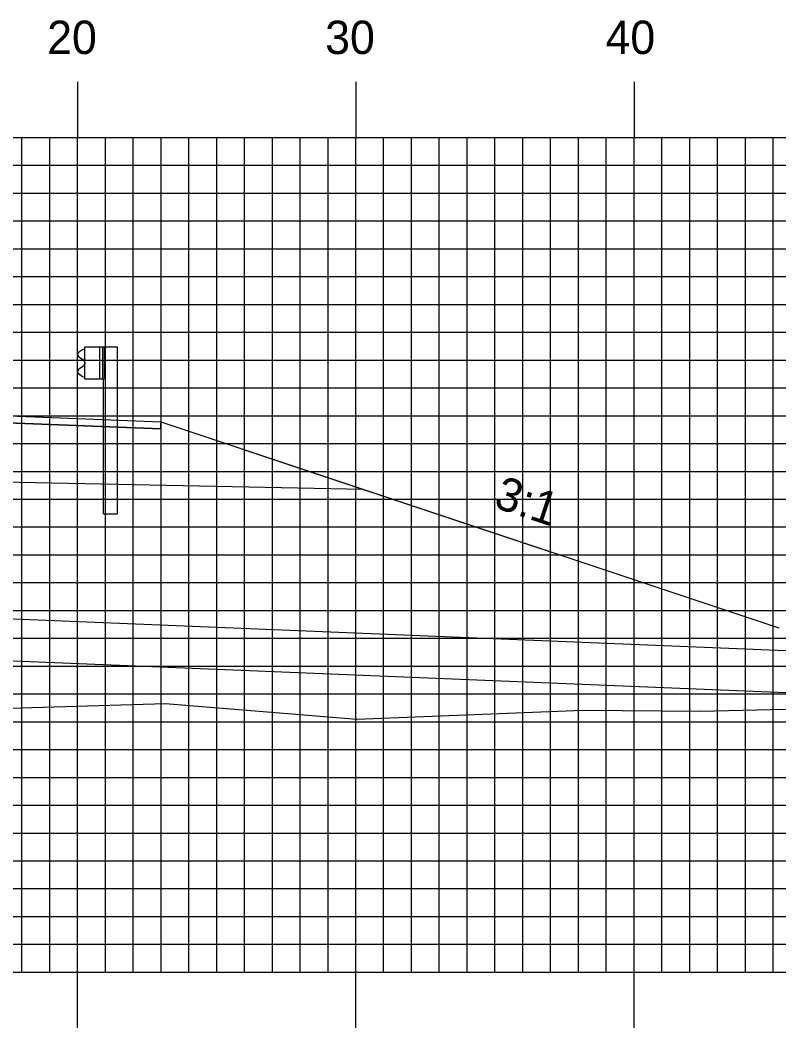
# Model space of a CAD drawing. Extents: x 1775564 to 1775907, y 442591 to 442811.
# Drawn here: x 1775747.65 to 1775774.91, y 442731.66 to 442767.88 of the extents above; entities that cross this region are included whole.
import ezdxf

# ---------------------------------------------------------------- set-up
doc = ezdxf.new("R2010")
doc.units = 0
for name, color, linetype in [('ANNOTATION', 7, 'Continuous'), ('D_Drainage_Culvert', 7, 'Continuous'), ('D_Guardrail_Beam_Rt', 7, 'Continuous'), ('D_Roadway_Centerline', 7, 'Continuous'), ('D_Roadway_Edge_Shoulder', 7, 'Continuous'), ('D_Roadway_SlopeLines', 7, 'Continuous'), ('D_Roadway_SubGrade', 7, 'Continuous'), ('H_V ANNOTATION', 7, 'Continuous'), ('MAJOR', 7, 'Continuous'), ('MINOR', 7, 'Continuous'), ('S_Roadway_Centerline', 7, 'Continuous')]:
    doc.layers.add(name, color=color, linetype=linetype)

msp = doc.modelspace()

# ---------------------------------------------------------------- linework, layer by layer
at = {"layer": 'D_Drainage_Culvert'}
for p, q in [((1775780.029, 442745.014), (1775684.11, 442748.945)), ((1775684.048, 442747.446), (1775779.968, 442743.515))]:
    msp.add_line(p, q, dxfattribs=at)
at = {"layer": 'D_Guardrail_Beam_Rt'}
for p, q in [((1775749.977, 442756.059), (1775749.903, 442756.044)), ((1775749.977, 442756.142), (1775750.665, 442756.142)), ((1775749.977, 442754.975), (1775749.977, 442756.142)), ((1775750.498, 442756.142), (1775750.498, 442754.975)), ((1775750.602, 442756.142), (1775750.602, 442754.975)), ((1775750.665, 442756.142), (1775751.136, 442756.142)), ((1775750.665, 442756.142), (1775750.665, 442754.975)), ((1775751.136, 442756.142), (1775751.136, 442750.142)), ((1775749.887, 442756.038), (1775749.744, 442755.938)), ((1775749.744, 442755.794), (1775749.939, 442755.658)), ((1775749.939, 442755.459), (1775749.744, 442755.323)), ((1775749.973, 442755.594), (1775749.973, 442755.524)), ((1775749.744, 442755.18), (1775749.887, 442755.08)), ((1775749.903, 442755.073), (1775749.977, 442755.059)), ((1775750.665, 442754.975), (1775749.977, 442754.975)), ((1775750.644, 442750.142), (1775750.644, 442754.975)), ((1775750.644, 442750.142), (1775751.136, 442750.142))]:
    msp.add_line(p, q, dxfattribs=at)
for centre, major_axis, start_param, end_param in [((1775749.911, 442756.004), (-0.0417, 0), 4.907132, 5.323254), ((1775749.794, 442755.866), (-0.0877, 0), 5.323254, 7.243116), ((1775749.794, 442755.252), (-0.0877, 0), 5.323254, 7.243116), ((1775749.894, 442755.594), (0.0789, 0), 0, 0.959931), ((1775749.894, 442755.524), (0.0789, 0), 5.323254, 6.283185), ((1775749.911, 442755.114), (-0.0417, 0), 0.959931, 1.376053)]:
    msp.add_ellipse(centre, major_axis=major_axis, ratio=0.995501, start_param=start_param, end_param=end_param, dxfattribs=at)
at = {"layer": 'D_Roadway_Centerline'}
msp.add_lwpolyline([(1775688.612, 442749.728), (1775693.913, 442750.903), (1775705.062, 442753.373), (1775705.062, 442753.373), (1775705.066, 442753.373), (1775709.262, 442753.541), (1775717.699, 442753.879), (1775717.706, 442753.879), (1775717.713, 442753.879), (1775724.629, 442754.017), (1775729.701, 442754.119), (1775729.706, 442754.119), (1775729.711, 442754.119), (1775741.706, 442753.879), (1775749.707, 442753.559), (1775752.706, 442753.439), (1775758.651, 442751.456), (1775758.652, 442751.456), (1775774.914, 442746.036)], dxfattribs=at)
at = {"layer": 'D_Roadway_Edge_Shoulder'}
msp.add_lwpolyline([(1775741.706, 442753.879), (1775749.706, 442753.559), (1775749.706, 442753.559), (1775752.706, 442753.439), (1775752.706, 442753.189), (1775741.706, 442753.629)], close=True, dxfattribs=at)
at = {"layer": 'D_Roadway_SlopeLines'}
msp.add_lwpolyline([(1775752.706, 442753.439), (1775774.912, 442746.037)], dxfattribs=at)
at = {"layer": 'D_Roadway_SubGrade'}
msp.add_lwpolyline([(1775741.706, 442753.629), (1775752.706, 442753.189), (1775752.706, 442753.439), (1775759.981, 442751.013), (1775741.706, 442751.378)], close=True, dxfattribs=at)
at = {"layer": 'MAJOR'}
for p, q in [((1775749.711, 442765.669), (1775749.711, 442763.665)), ((1775759.711, 442765.669), (1775759.711, 442763.665)), ((1775769.711, 442765.669), (1775769.711, 442763.665)), ((1775589.711, 442763.665), (1775869.711, 442763.665)), ((1775589.711, 442763.665), (1775869.711, 442763.665)), ((1775749.711, 442733.665), (1775749.711, 442763.665)), ((1775759.711, 442733.665), (1775759.711, 442763.665)), ((1775769.711, 442733.665), (1775769.711, 442763.665)), ((1775589.711, 442758.665), (1775869.711, 442758.665)), ((1775589.711, 442753.665), (1775869.711, 442753.665)), ((1775589.711, 442748.665), (1775869.711, 442748.665)), ((1775589.711, 442743.665), (1775869.711, 442743.665)), ((1775589.711, 442738.665), (1775869.711, 442738.665)), ((1775589.711, 442733.665), (1775869.711, 442733.665)), ((1775589.711, 442733.665), (1775869.711, 442733.665)), ((1775749.711, 442731.661), (1775749.711, 442733.665)), ((1775759.711, 442731.661), (1775759.711, 442733.665)), ((1775769.711, 442731.661), (1775769.711, 442733.665))]:
    msp.add_line(p, q, dxfattribs=at)
at = {"layer": 'MINOR'}
for p, q in [((1775747.711, 442733.665), (1775747.711, 442763.665)), ((1775748.711, 442733.665), (1775748.711, 442763.665)), ((1775750.711, 442733.665), (1775750.711, 442763.665)), ((1775751.711, 442733.665), (1775751.711, 442763.665)), ((1775752.711, 442733.665), (1775752.711, 442763.665)), ((1775753.711, 442733.665), (1775753.711, 442763.665)), ((1775754.711, 442733.665), (1775754.711, 442763.665)), ((1775755.711, 442733.665), (1775755.711, 442763.665)), ((1775756.711, 442733.665), (1775756.711, 442763.665)), ((1775757.711, 442733.665), (1775757.711, 442763.665)), ((1775758.711, 442733.665), (1775758.711, 442763.665)), ((1775760.711, 442733.665), (1775760.711, 442763.665)), ((1775761.711, 442733.665), (1775761.711, 442763.665)), ((1775762.711, 442733.665), (1775762.711, 442763.665)), ((1775763.711, 442733.665), (1775763.711, 442763.665)), ((1775764.711, 442733.665), (1775764.711, 442763.665)), ((1775765.711, 442733.665), (1775765.711, 442763.665)), ((1775766.711, 442733.665), (1775766.711, 442763.665)), ((1775767.711, 442733.665), (1775767.711, 442763.665)), ((1775768.711, 442733.665), (1775768.711, 442763.665)), ((1775770.711, 442733.665), (1775770.711, 442763.665)), ((1775771.711, 442733.665), (1775771.711, 442763.665)), ((1775772.711, 442733.665), (1775772.711, 442763.665)), ((1775773.711, 442733.665), (1775773.711, 442763.665)), ((1775774.711, 442733.665), (1775774.711, 442763.665)), ((1775589.711, 442762.665), (1775869.711, 442762.665)), ((1775589.711, 442761.665), (1775869.711, 442761.665)), ((1775589.711, 442760.665), (1775869.711, 442760.665)), ((1775589.711, 442759.665), (1775869.711, 442759.665)), ((1775589.711, 442757.665), (1775869.711, 442757.665)), ((1775589.711, 442756.665), (1775869.711, 442756.665)), ((1775589.711, 442755.665), (1775869.711, 442755.665)), ((1775589.711, 442754.665), (1775869.711, 442754.665)), ((1775589.711, 442752.665), (1775869.711, 442752.665)), ((1775589.711, 442751.665), (1775869.711, 442751.665)), ((1775589.711, 442750.665), (1775869.711, 442750.665)), ((1775589.711, 442749.665), (1775869.711, 442749.665)), ((1775589.711, 442747.665), (1775869.711, 442747.665)), ((1775589.711, 442746.665), (1775869.711, 442746.665)), ((1775589.711, 442745.665), (1775869.711, 442745.665)), ((1775589.711, 442744.665), (1775869.711, 442744.665)), ((1775589.711, 442742.665), (1775869.711, 442742.665)), ((1775589.711, 442741.665), (1775869.711, 442741.665)), ((1775589.711, 442740.665), (1775869.711, 442740.665)), ((1775589.711, 442739.665), (1775869.711, 442739.665)), ((1775589.711, 442737.665), (1775869.711, 442737.665)), ((1775589.711, 442736.665), (1775869.711, 442736.665)), ((1775589.711, 442735.665), (1775869.711, 442735.665)), ((1775589.711, 442734.665), (1775869.711, 442734.665))]:
    msp.add_line(p, q, dxfattribs=at)
at = {"layer": 'S_Roadway_Centerline'}
msp.add_lwpolyline([(1775672.883, 442748.755), (1775679.808, 442747.944), (1775686.03, 442747.238), (1775692.236, 442746.554), (1775708.023, 442744.873), (1775714.564, 442744.146), (1775721.037, 442743.68), (1775731.103, 442743.28), (1775737.266, 442742.856), (1775752.875, 442743.315), (1775759.742, 442742.762), (1775767.868, 442743.076), (1775772.092, 442743.041), (1775776.145, 442743.138), (1775784.349, 442743.456), (1775792.415, 442743.856)], dxfattribs=at)

# ---------------------------------------------------------------- texts
at = {"layer": 'ANNOTATION'}
msp.add_text('3:1', height=1.2, rotation=341.5667, dxfattribs=at).set_placement((1775764.624, 442750.385))
at = {"layer": 'H_V ANNOTATION'}
for s, p in [('20', (1775748.619, 442766.665)), ('30', (1775758.609, 442766.665)), ('40', (1775768.684, 442766.665))]:
    msp.add_text(s, height=1.2, dxfattribs=at).set_placement(p)

doc.saveas('drawing.dxf')
